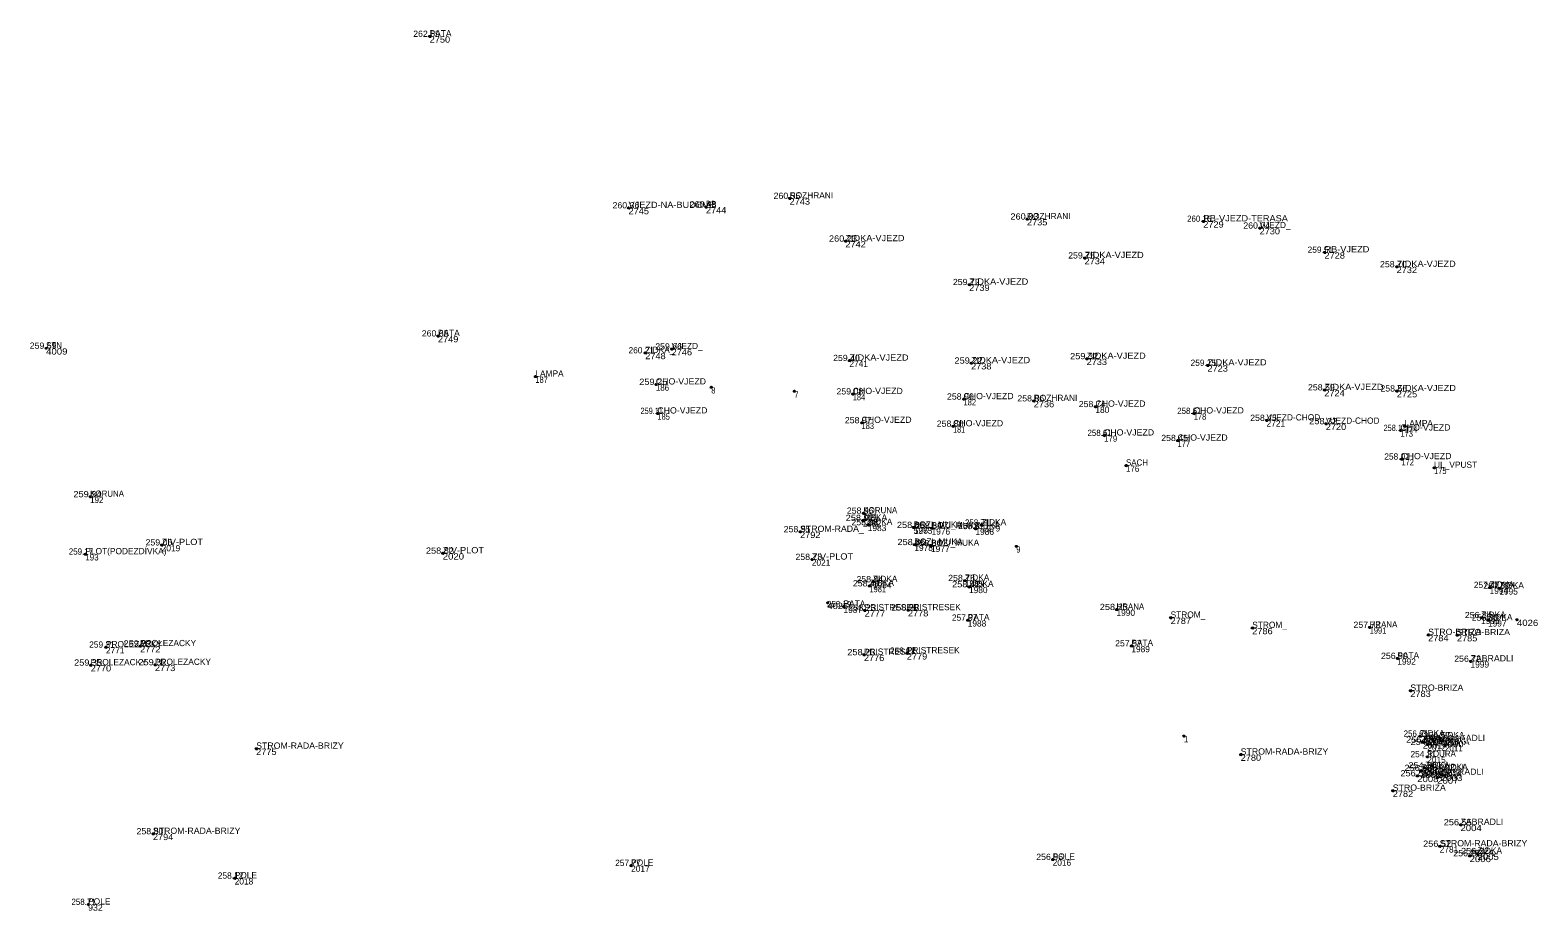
# Model space of a CAD drawing. Extents: x -565336 to -561834, y -1146819 to -1145270.
# Drawn here: x -562839.1 to -562756.9, y -1145694.3 to -1145646.3 of the extents above; entities that cross this region are included whole.
import ezdxf
from ezdxf.enums import TextEntityAlignment as Align

# ---------------------------------------------------------------- set-up
doc = ezdxf.new("R2010")
doc.units = 0
doc.header["$LTSCALE"] = 0.14
doc.header["$PDMODE"] = 32
doc.header["$PDSIZE"] = 0.07
for name, color, linetype in [('40', 7, 'Continuous'), ('43', 7, 'Continuous'), ('44', 7, 'Continuous'), ('45', 7, 'Continuous')]:
    doc.layers.add(name, color=color, linetype=linetype)

msp = doc.modelspace()

# ---------------------------------------------------------------- linework, layer by layer
at = {"layer": '40'}
for p in [(-562817.35, -1145646.6), (-562806.51, -1145655.95), (-562802.29, -1145655.9), (-562797.73, -1145655.43), (-562784.79, -1145656.56), (-562775.18, -1145656.68), (-562772.11, -1145657.05), (-562794.69, -1145657.76), (-562768.57, -1145658.37), (-562781.65, -1145658.68), (-562764.64, -1145659.16), (-562787.94, -1145660.13), (-562816.9, -1145662.93), (-562838.26, -1145663.6), (-562805.6, -1145663.85), (-562804.16, -1145663.64), (-562781.54, -1145664.17), (-562794.47, -1145664.27), (-562787.84, -1145664.41), (-562774.95, -1145664.53), (-562811.59, -1145665.14), (-562805.02, -1145665.57), (-562802, -1145665.72), (-562797.47, -1145665.94), (-562794.29, -1145666.09), (-562788.25, -1145666.37), (-562784.42, -1145666.47), (-562768.58, -1145665.87), (-562764.63, -1145665.93), (-562804.94, -1145667.15), (-562781.06, -1145666.78), (-562775.7, -1145667.15), (-562793.81, -1145667.66), (-562788.82, -1145667.85), (-562771.73, -1145667.53), (-562768.5, -1145667.71), (-562764.43, -1145668.08), (-562764.2, -1145667.85), (-562780.59, -1145668.35), (-562776.58, -1145668.63), (-562764.38, -1145669.64), (-562779.39, -1145669.99), (-562762.6, -1145670.11), (-562835.86, -1145671.69), (-562793.75, -1145672.98), (-562793.71, -1145672.59), (-562797.16, -1145673.6), (-562793.47, -1145673.22), (-562790.98, -1145673.36), (-562790.96, -1145673.37), (-562789.99, -1145673.41), (-562787.6, -1145673.43), (-562787.26, -1145673.24), (-562836.12, -1145674.82), (-562831.96, -1145674.32), (-562816.64, -1145674.77), (-562790.93, -1145674.3), (-562790.02, -1145674.36), (-562785.37, -1145674.39), (-562796.52, -1145675.11), (-562793.19, -1145676.33), (-562788.18, -1145676.26), (-562793.38, -1145676.55), (-562787.95, -1145676.6), (-562759.57, -1145676.64), (-562759.04, -1145676.68), (-562795.66, -1145677.47), (-562794.79, -1145677.68), (-562793.64, -1145677.88), (-562791.28, -1145677.87), (-562779.91, -1145677.84), (-562788.02, -1145678.42), (-562776.96, -1145678.28), (-562772.51, -1145678.84), (-562766.11, -1145678.81), (-562760.03, -1145678.28), (-562759.66, -1145678.42), (-562758.08, -1145678.39), (-562762.92, -1145679.22), (-562761.35, -1145679.23), (-562835, -1145679.89), (-562833.14, -1145679.83), (-562793.68, -1145680.3), (-562791.34, -1145680.22), (-562779.1, -1145679.82), (-562764.6, -1145680.5), (-562835.83, -1145680.87), (-562832.33, -1145680.85), (-562760.61, -1145680.66), (-562763.89, -1145682.26), (-562826.81, -1145685.42), (-562776.24, -1145684.73), (-562763.36, -1145684.74), (-562763.21, -1145685.07), (-562762.97, -1145685.19), (-562762.28, -1145684.84), (-562762.15, -1145685), (-562762, -1145685.22), (-562773.14, -1145685.74), (-562762.97, -1145685.86), (-562763.52, -1145686.9), (-562763.3, -1145686.61), (-562763.09, -1145686.47), (-562762.43, -1145686.99), (-562762.22, -1145686.84), (-562762.1, -1145686.58), (-562764.85, -1145687.71), (-562761.16, -1145689.57), (-562832.44, -1145690.06), (-562762.29, -1145690.74), (-562760.66, -1145691.26), (-562760.23, -1145691.14), (-562806.37, -1145691.79), (-562783.39, -1145691.46), (-562827.98, -1145692.48), (-562835.97, -1145693.91)]:
    msp.add_point(p, dxfattribs=at)

# ---------------------------------------------------------------- texts
at = {"layer": '43'}
for s, width, p in [('2750', 1.1, (-562817.35, -1145646.94)), ('2744', 1.1, (-562802.29, -1145656.24)), ('2743', 1.1, (-562797.73, -1145655.77)), ('2745', 1.1, (-562806.51, -1145656.29)), ('2735', 1.1, (-562784.79, -1145656.9)), ('2729', 1.1, (-562775.18, -1145657.02)), ('2730', 1.1, (-562772.11, -1145657.39)), ('2742', 1.1, (-562794.69, -1145658.1)), ('2728', 1.1, (-562768.57, -1145658.71)), ('2734', 1.1, (-562781.65, -1145659.02)), ('2732', 1.1, (-562764.64, -1145659.5)), ('2739', 1.1, (-562787.94, -1145660.47)), ('2749', 1.1, (-562816.9, -1145663.27)), ('4009', 1.15, (-562838.26, -1145663.94)), ('2748', 1.1, (-562805.6, -1145664.19)), ('2746', 1.1, (-562804.16, -1145663.98)), ('2738', 1.1, (-562787.84, -1145664.75)), ('2733', 1.1, (-562781.54, -1145664.51)), ('2723', 1.1, (-562774.95, -1145664.87)), ('187', 0.9, (-562811.59, -1145665.48)), ('186', 0.95, (-562805.02, -1145665.91)), ('8', 0.75, (-562802, -1145666.06)), ('7', 0.75, (-562797.47, -1145666.28)), ('184', 0.9, (-562794.29, -1145666.43)), ('182', 0.9, (-562788.25, -1145666.71)), ('2736', 1.1, (-562784.42, -1145666.81)), ('2724', 1.1, (-562768.58, -1145666.21)), ('2725', 1.1, (-562764.63, -1145666.27)), ('185', 0.9, (-562804.94, -1145667.49)), ('178', 0.9, (-562775.7, -1145667.49)), ('183', 0.9, (-562793.81, -1145668)), ('181', 0.8, (-562788.82, -1145668.19)), ('2720', 1.1, (-562768.5, -1145668.05)), ('173', 0.9, (-562764.43, -1145668.42)), ('174', 0.9, (-562764.2, -1145668.19)), ('179', 0.95, (-562780.59, -1145668.69)), ('177', 0.9, (-562776.58, -1145668.97)), ('172', 0.9, (-562764.38, -1145669.98)), ('176', 0.95, (-562779.39, -1145670.33)), ('175', 0.9, (-562762.6, -1145670.45)), ('192', 0.95, (-562835.86, -1145672.03)), ('194', 0.95, (-562793.71, -1145672.93)), ('2792', 1.1, (-562797.16, -1145673.94)), ('526', 1.05, (-562790.98, -1145673.7)), ('193', 0.95, (-562836.12, -1145675.16)), ('2020', 1.15, (-562816.64, -1145675.11)), ('9', 0.75, (-562785.37, -1145674.73)), ('1981', 0.9, (-562793.38, -1145676.89)), ('4025', 1.1, (-562795.66, -1145677.81)), ('2777', 1.1, (-562793.64, -1145678.22)), ('2778', 1.1, (-562791.28, -1145678.21)), ('2787', 1.1, (-562776.96, -1145678.62)), ('2786', 1.1, (-562772.51, -1145679.18)), ('1991', 0.9, (-562766.11, -1145679.15)), ('4026', 1.15, (-562758.08, -1145678.73)), ('2784', 1.1, (-562762.92, -1145679.56)), ('2785', 1.1, (-562761.35, -1145679.57)), ('2772', 1.1, (-562833.14, -1145680.17)), ('2776', 1.1, (-562793.68, -1145680.64)), ('2779', 1.1, (-562791.34, -1145680.56)), ('2770', 1.1, (-562835.83, -1145681.21)), ('2773', 1.1, (-562832.33, -1145681.19)), ('2783', 1.1, (-562763.89, -1145682.6)), ('2775', 1.1, (-562826.81, -1145685.76)), ('2009', 1.15, (-562763.36, -1145685.08)), ('2001', 1.05, (-562763.21, -1145685.41)), ('2010', 1.05, (-562762.28, -1145685.18)), ('2000', 1.15, (-562762.15, -1145685.34)), ('2011', 0.95, (-562762, -1145685.56)), ('2780', 1.1, (-562773.14, -1145686.08)), ('2008', 1.15, (-562763.52, -1145687.24)), ('2002', 1.15, (-562763.3, -1145686.95)), ('2007', 1.15, (-562762.43, -1145687.33)), ('2003', 1.15, (-562762.22, -1145687.18)), ('2782', 1.1, (-562764.85, -1145688.05)), ('2004', 1.15, (-562761.16, -1145689.91)), ('2794', 1.1, (-562832.44, -1145690.4)), ('2006', 1.15, (-562760.66, -1145691.6)), ('2005', 1.15, (-562760.23, -1145691.48)), ('932', 1.05, (-562835.97, -1145694.25))]:
    msp.add_text(s, height=0.34, dxfattribs=dict(at, width=width)).set_placement(p)
for s, p in [('2741', (-562794.47, -1145664.61)), ('180', (-562781.06, -1145667.12)), ('2721', (-562771.73, -1145667.87)), ('1982', (-562793.75, -1145673.32)), ('1983', (-562793.47, -1145673.56)), ('1975', (-562790.96, -1145673.71)), ('1976', (-562789.99, -1145673.75)), ('1986', (-562787.6, -1145673.77)), ('1979', (-562787.26, -1145673.58)), ('2019', (-562831.96, -1145674.66)), ('1978', (-562790.93, -1145674.64)), ('1977', (-562790.02, -1145674.7)), ('2021', (-562796.52, -1145675.45)), ('1984', (-562793.19, -1145676.67)), ('1985', (-562788.18, -1145676.6)), ('1980', (-562787.95, -1145676.94)), ('1994', (-562759.57, -1145676.98)), ('1995', (-562759.04, -1145677.02)), ('1987', (-562794.79, -1145678.02)), ('1990', (-562779.91, -1145678.18)), ('1988', (-562788.02, -1145678.76)), ('1996', (-562760.03, -1145678.62)), ('1997', (-562759.66, -1145678.76)), ('2771', (-562835, -1145680.23)), ('1989', (-562779.1, -1145680.16)), ('1992', (-562764.6, -1145680.84)), ('1999', (-562760.61, -1145681)), ('1', (-562776.24, -1145685.07)), ('2012', (-562762.97, -1145685.53)), ('2015', (-562762.97, -1145686.2)), ('2013', (-562763.09, -1145686.81)), ('2014', (-562762.1, -1145686.92)), ('2781', (-562762.29, -1145691.08)), ('2017', (-562806.37, -1145692.13)), ('2016', (-562783.39, -1145691.8)), ('2018', (-562827.98, -1145692.82))]:
    msp.add_text(s, height=0.34, dxfattribs=at).set_placement(p)
at = {"layer": '44'}
for s, width, p in [('262.69', 1.05, (-562817.52, -1145646.624)), ('260.36', 1.05, (-562806.6535, -1145655.974)), ('260.48', 1.05, (-562802.4465, -1145655.924)), ('260.55', 1.05, (-562797.872, -1145655.454)), ('260.03', 1.1, (-562784.928, -1145656.584)), ('260.15', 0.95, (-562775.401, -1145656.704)), ('260.04', 1.05, (-562772.2655, -1145657.074)), ('260.23', 1.1, (-562794.8185, -1145657.784)), ('259.75', 1.05, (-562781.8135, -1145658.704)), ('258.70', 1.05, (-562764.813, -1145659.184)), ('259.72', 1.05, (-562788.098, -1145660.154)), ('259.69', 1.05, (-562838.4245, -1145663.624)), ('260.65', 1.05, (-562817.0515, -1145662.954)), ('259.66', 1.05, (-562804.3245, -1145663.664)), ('259.40', 1.05, (-562794.6295, -1145664.294)), ('259.22', 1.1, (-562787.9755, -1145664.434)), ('259.32', 1.1, (-562781.6725, -1145664.194)), ('259.25', 1.1, (-562805.1605, -1145665.594)), ('259.08', 1.05, (-562794.4455, -1145666.114)), ('258.59', 1.05, (-562768.741, -1145665.894)), ('258.56', 1.05, (-562764.791, -1145665.954)), ('258.96', 1.05, (-562788.42, -1145666.394)), ('258.86', 1.05, (-562784.585, -1145666.494)), ('258.74', 1.05, (-562781.2385, -1145666.804)), ('259.11', 0.85, (-562805.244, -1145667.174)), ('258.97', 1.05, (-562793.9885, -1145667.684)), ('258.61', 0.95, (-562775.94, -1145667.174)), ('258.45', 1.05, (-562771.891, -1145667.554)), ('258.32', 1.1, (-562768.638, -1145667.734)), ('258.80', 1.05, (-562788.9795, -1145667.874)), ('258.61', 0.95, (-562780.83, -1145668.374)), ('258.11', 0.85, (-562764.7395, -1145668.104)), ('258.45', 1.05, (-562776.741, -1145668.654)), ('259.34', 1.1, (-562836.0075, -1145671.714)), ('258.96', 1.05, (-562793.88, -1145672.614)), ('258.92', 1.1, (-562793.9055, -1145673.004)), ('258.88', 1.05, (-562793.631, -1145673.244)), ('258.85', 1.1, (-562791.1155, -1145673.394)), ('258.84', 1.05, (-562790.155, -1145673.434)), ('258.71', 0.95, (-562787.508, -1145673.264)), ('259.05', 1.05, (-562832.11, -1145674.344)), ('258.95', 1.05, (-562797.321, -1145673.624)), ('258.85', 1.1, (-562791.0855, -1145674.324)), ('259.17', 0.95, (-562836.3625, -1145674.844)), ('258.82', 1.1, (-562816.79, -1145674.794)), ('258.73', 1.05, (-562796.681, -1145675.134)), ('258.84', 1.05, (-562790.185, -1145674.384)), ('258.49', 1.05, (-562793.55, -1145676.574)), ('258.84', 1.05, (-562793.355, -1145676.354)), ('258.78', 1.05, (-562788.3545, -1145676.284)), ('258.42', 1.1, (-562788.1055, -1145676.624)), ('257.50', 1.05, (-562759.182, -1145676.704)), ('258.19', 0.95, (-562795.03, -1145677.704)), ('258.23', 1.1, (-562793.778, -1145677.904)), ('258.28', 1.1, (-562791.4315, -1145677.894)), ('258.25', 1.1, (-562780.056, -1145677.864)), ('256.84', 1.05, (-562760.1895, -1145678.304)), ('256.80', 1.05, (-562759.814, -1145678.444)), ('257.72', 1.05, (-562766.26, -1145678.834)), ('259.32', 1.1, (-562833.2725, -1145679.854)), ('257.57', 1.05, (-562779.2555, -1145679.844)), ('259.35', 1.1, (-562835.968, -1145680.894)), ('259.32', 1.1, (-562832.4625, -1145680.874)), ('258.23', 1.1, (-562793.818, -1145680.324)), ('256.90', 1.05, (-562764.7595, -1145680.524)), ('256.72', 1.05, (-562760.768, -1145680.684)), ('256.61', 0.95, (-562763.5945, -1145684.764)), ('256.57', 1.05, (-562762.4435, -1145684.864)), ('256.66', 1.05, (-562762.3145, -1145685.024)), ('256.63', 1.1, (-562763.3575, -1145685.094)), ('254.20', 1.1, (-562763.1145, -1145685.214)), ('254.20', 1.1, (-562762.1445, -1145685.244)), ('256.63', 1.1, (-562763.4475, -1145686.634)), ('254.20', 1.1, (-562763.2345, -1145686.494)), ('254.22', 1.1, (-562762.2355, -1145686.604)), ('256.55', 1.1, (-562763.666, -1145686.924)), ('256.53', 1.1, (-562762.568, -1145687.014)), ('256.62', 1.05, (-562762.37, -1145686.864)), ('256.55', 1.1, (-562761.306, -1145689.594)), ('258.80', 1.05, (-562832.5995, -1145690.084)), ('256.52', 1.1, (-562762.4305, -1145690.764)), ('256.96', 1.05, (-562783.5545, -1145691.484)), ('256.27', 1.05, (-562760.818, -1145691.284)), ('256.22', 1.1, (-562760.3655, -1145691.164)), ('258.71', 0.95, (-562836.218, -1145693.934))]:
    msp.add_text(s, height=0.34, dxfattribs=dict(at, width=width)).set_placement(p, align=Align.CENTER)
for s, p in [('259.51', (-562768.795, -1145658.394)), ('260.21', (-562805.8155, -1145663.874)), ('259.15', (-562775.175, -1145664.554)), ('258.01', (-562764.6145, -1145669.664)), ('258.81', (-562787.8345, -1145673.454)), ('257.47', (-562759.735, -1145676.664)), ('257.97', (-562788.185, -1145678.444)), ('259.31', (-562835.217, -1145679.914)), ('258.12', (-562791.565, -1145680.244)), ('254.31', (-562763.187, -1145685.884)), ('257.77', (-562806.543, -1145691.814)), ('258.12', (-562828.205, -1145692.504))]:
    msp.add_text(s, height=0.34, dxfattribs=at).set_placement(p, align=Align.CENTER)
at = {"layer": '45'}
for s, p in [('PATA', (-562817.35, -1145646.6)), ('ROZHRANI', (-562797.73, -1145655.43)), ('ROZHRANI', (-562784.79, -1145656.56)), ('VJEZD_', (-562772.11, -1145657.05)), ('PATA', (-562816.9, -1145662.93)), ('VJEZD_', (-562804.16, -1145663.64)), ('ZIDKA_', (-562805.6, -1145663.85)), ('LAMPA', (-562811.59, -1145665.14)), ('ROZHRANI', (-562784.42, -1145666.47)), ('VJEZD-CHOD', (-562771.73, -1145667.53)), ('VJEZD-CHOD', (-562768.5, -1145667.71)), ('LAMPA', (-562764.2, -1145667.85)), ('UL_VPUST', (-562762.6, -1145670.11)), ('ZIDKA', (-562793.75, -1145672.98)), ('ZIDKA', (-562793.47, -1145673.22)), ('BOZI_MUKA', (-562790.96, -1145673.37)), ('BOZI_MUKA', (-562789.99, -1145673.41)), ('ZIDKA', (-562787.6, -1145673.43)), ('ZIDKA', (-562787.26, -1145673.24)), ('BOZI_MUKA', (-562790.93, -1145674.3)), ('PLOT(PODEZDÍVKA)', (-562836.12, -1145674.82)), ('BOZI_MUKA', (-562790.02, -1145674.36)), ('ZIDKA', (-562793.38, -1145676.55)), ('ZIDKA', (-562793.19, -1145676.33)), ('ZIDKA', (-562788.18, -1145676.26)), ('ZIDKA', (-562787.95, -1145676.6)), ('ZIDKA', (-562759.57, -1145676.64)), ('ZIDKA', (-562759.04, -1145676.68)), ('PATA', (-562794.79, -1145677.68)), ('PRISTRESEK', (-562793.64, -1145677.88)), ('PRISTRESEK', (-562791.28, -1145677.87)), ('PATA', (-562788.02, -1145678.42)), ('STROM_', (-562776.96, -1145678.28)), ('ZIDKA', (-562760.03, -1145678.28)), ('ZIDKA', (-562759.66, -1145678.42)), ('STROM_', (-562772.51, -1145678.84)), ('PROLEZACKY', (-562835, -1145679.89)), ('PROLEZACKY', (-562833.14, -1145679.83)), ('PATA', (-562779.1, -1145679.82)), ('PROLEZACKY', (-562835.83, -1145680.87)), ('PROLEZACKY', (-562832.33, -1145680.85)), ('PRISTRESEK', (-562793.68, -1145680.3)), ('PRISTRESEK', (-562791.34, -1145680.22)), ('PATA', (-562764.6, -1145680.5)), ('ZIDKA', (-562763.36, -1145684.74)), ('ZIDKA', (-562762.28, -1145684.84)), ('ZIDKA', (-562762.97, -1145685.19)), ('ZIDKA', (-562762, -1145685.22)), ('ZIDKA', (-562763.09, -1145686.47)), ('ZIDKA', (-562762.1, -1145686.58)), ('ZIDKA', (-562763.52, -1145686.9)), ('ZIDKA', (-562762.43, -1145686.99)), ('POLE', (-562783.39, -1145691.46)), ('ZIDKA', (-562760.66, -1145691.26)), ('ZIDKA', (-562760.23, -1145691.14)), ('POLE', (-562806.37, -1145691.79)), ('POLE', (-562827.98, -1145692.48)), ('POLE', (-562835.97, -1145693.91))]:
    msp.add_text(s, height=0.34, dxfattribs=at).set_placement(p)
for s, width, p in [('VJEZD-NA-BUDOVE', 1.1, (-562806.51, -1145655.95)), ('RB', 0.85, (-562802.29, -1145655.9)), ('RB-VJEZD-TERASA', 1.1, (-562775.18, -1145656.68)), ('ZIDKA-VJEZD', 1.1, (-562794.69, -1145657.76)), ('ZIDKA-VJEZD', 1.1, (-562781.65, -1145658.68)), ('RB-VJEZD', 1.1, (-562768.57, -1145658.37)), ('ZIDKA-VJEZD', 1.1, (-562764.64, -1145659.16)), ('ZIDKA-VJEZD', 1.1, (-562787.94, -1145660.13)), ('STN', 0.95, (-562838.26, -1145663.6)), ('ZIDKA-VJEZD', 1.1, (-562794.47, -1145664.27)), ('ZIDKA-VJEZD', 1.1, (-562787.84, -1145664.41)), ('ZIDKA-VJEZD', 1.1, (-562781.54, -1145664.17)), ('ZIDKA-VJEZD', 1.1, (-562774.95, -1145664.53)), ('CHO-VJEZD', 1.05, (-562805.02, -1145665.57)), ('CHO-VJEZD', 1.05, (-562794.29, -1145666.09)), ('ZIDKA-VJEZD', 1.1, (-562768.58, -1145665.87)), ('ZIDKA-VJEZD', 1.1, (-562764.63, -1145665.93)), ('CHO-VJEZD', 1.05, (-562788.25, -1145666.37)), ('CHO-VJEZD', 1.05, (-562781.06, -1145666.78)), ('CHO-VJEZD', 1.05, (-562804.94, -1145667.15)), ('CHO-VJEZD', 1.05, (-562793.81, -1145667.66)), ('CHO-VJEZD', 1.05, (-562775.7, -1145667.15)), ('CHO-VJEZD', 1.05, (-562788.82, -1145667.85)), ('CHO-VJEZD', 1.05, (-562780.59, -1145668.35)), ('CHO-VJEZD', 1.05, (-562764.43, -1145668.08)), ('CHO-VJEZD', 1.05, (-562776.58, -1145668.63)), ('SACH', 0.95, (-562779.39, -1145669.99)), ('CHO-VJEZD', 1.05, (-562764.38, -1145669.64)), ('KORUNA', 0.95, (-562835.86, -1145671.69)), ('KORUNA', 0.95, (-562793.71, -1145672.59)), ('ZIV-PLOT', 1.1, (-562831.96, -1145674.32)), ('STROM-RADA_', 1.05, (-562797.16, -1145673.6)), ('ZIV-PLOT', 1.1, (-562816.64, -1145674.77)), ('ZIV-PLOT', 1.1, (-562796.52, -1145675.11)), ('HRANA', 0.95, (-562779.91, -1145677.84)), ('HRANA', 0.95, (-562766.11, -1145678.81)), ('STRO-BRIZA', 1.05, (-562762.92, -1145679.22)), ('STRO-BRIZA', 1.05, (-562761.35, -1145679.23)), ('ZABRADLI', 1.05, (-562760.61, -1145680.66)), ('STRO-BRIZA', 1.05, (-562763.89, -1145682.26)), ('ZABRADLI', 1.05, (-562762.15, -1145685)), ('STROM-RADA-BRIZY', 1.05, (-562826.81, -1145685.42)), ('STROM-RADA-BRIZY', 1.05, (-562773.14, -1145685.74)), ('ZABRADLI', 1.05, (-562763.21, -1145685.07)), ('ZABRADLI', 1.05, (-562763.3, -1145686.61)), ('ROURA', 0.95, (-562762.97, -1145685.86)), ('ZABRADLI', 1.05, (-562762.22, -1145686.84)), ('STRO-BRIZA', 1.05, (-562764.85, -1145687.71)), ('ZABRADLI', 1.05, (-562761.16, -1145689.57)), ('STROM-RADA-BRIZY', 1.05, (-562832.44, -1145690.06)), ('STROM-RADA-BRIZY', 1.05, (-562762.29, -1145690.74))]:
    msp.add_text(s, height=0.34, dxfattribs=dict(at, width=width)).set_placement(p)

doc.saveas('drawing.dxf')
